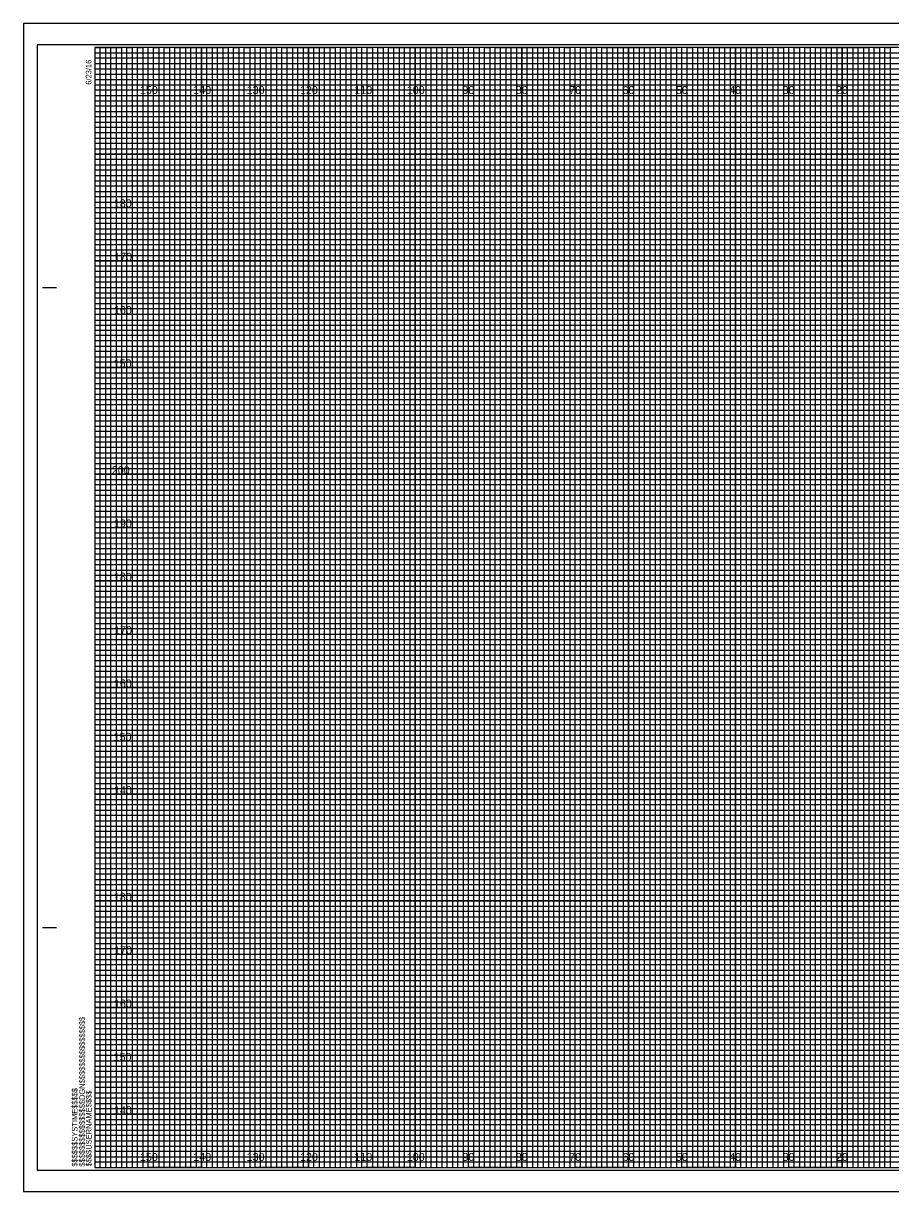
# Model space of a CAD drawing. Extents: x -13 to 323, y -5 to 434.
# Drawn here: x -13.4 to 149.1, y -4.5 to 214.5 of the extents above; entities that cross this region are included whole.
import ezdxf

# ---------------------------------------------------------------- set-up
doc = ezdxf.new("R2010")
doc.units = 0
for name, color, linetype in [('Exist Cross Section Cell', 7, 'Continuous'), ('Exist XS Center Line Elevation Label', 7, 'Continuous'), ('Exist XS Ground Line', 7, 'Continuous'), ('Prop CMT Guardrail Graphics', 7, 'Continuous'), ('Prop CMT Pvmt Course 1', 7, 'Continuous'), ('Prop CMT Pvmt Course 2', 7, 'Continuous'), ('Prop CMT Pvmt Course 3', 7, 'Continuous'), ('Prop CMT Shld Paved Course 1', 7, 'Continuous'), ('Prop CMT Shld Paved Course 2', 7, 'Continuous'), ('Prop CMT Subgrade Earthwork', 7, 'Continuous'), ('Scratch_Level_0', 7, 'Continuous')]:
    doc.layers.add(name, color=color, linetype=linetype)

msp = doc.modelspace()

# ---------------------------------------------------------------- linework, layer by layer
at = {"layer": 'Exist XS Center Line Elevation Label'}
for points in [[(0, 210), (5, 210), (5, 0), (15, 0), (15, 210), (25, 210), (25, 0), (35, 0), (35, 210), (45, 210), (45, 0), (55, 0), (55, 210), (65, 210), (65, 0), (75, 0), (75, 210), (85, 210), (85, 0), (95, 0), (95, 210), (105, 210), (105, 0), (115, 0), (115, 210), (125, 210), (125, 0), (135, 0), (135, 210), (145, 210), (145, 0), (155, 0)], [(0, 205), (275, 205)], [(0, 185), (320, 185), (320, 195), (0, 195)], [(0, 165), (320, 165), (320, 175), (0, 175)], [(0, 145), (320, 145), (320, 155), (0, 155)], [(0, 125), (320, 125), (320, 135), (0, 135)], [(0, 105), (320, 105), (320, 115), (0, 115)], [(0, 85), (320, 85), (320, 95), (0, 95)], [(0, 65), (320, 65), (320, 75), (0, 75)], [(0, 45), (320, 45), (320, 55), (0, 55)], [(0, 25), (320, 25), (320, 35), (0, 35)], [(0, 5), (320, 5), (320, 15), (0, 15)]]:
    msp.add_lwpolyline(points, dxfattribs=at)
at = {"layer": 'Exist XS Ground Line'}
for p, q in [((10, 210), (0, 210)), ((10, 0), (10, 210)), ((30, 210), (20, 210)), ((20, 210), (20, 0)), ((30, 0), (30, 210)), ((50, 210), (40, 210)), ((40, 210), (40, 0)), ((50, 0), (50, 210)), ((70, 210), (60, 210)), ((60, 210), (60, 0)), ((70, 0), (70, 210)), ((90, 210), (80, 210)), ((80, 210), (80, 0)), ((90, 0), (90, 210)), ((110, 210), (100, 210)), ((100, 210), (100, 0)), ((110, 0), (110, 210)), ((130, 210), (120, 210)), ((120, 210), (120, 0)), ((130, 0), (130, 210)), ((150, 210), (140, 210)), ((140, 210), (140, 0)), ((20, 0), (10, 0)), ((40, 0), (30, 0)), ((60, 0), (50, 0)), ((80, 0), (70, 0)), ((100, 0), (90, 0)), ((120, 0), (110, 0)), ((140, 0), (130, 0))]:
    msp.add_line(p, q, dxfattribs=at)
for points in [[(0, 200), (320, 200), (320, 190), (0, 190)], [(0, 180), (320, 180), (320, 170), (0, 170)], [(0, 160), (320, 160), (320, 150), (0, 150)], [(0, 140), (320, 140), (320, 130), (0, 130)], [(0, 120), (320, 120), (320, 110), (0, 110)], [(0, 100), (320, 100), (320, 90), (0, 90)], [(0, 80), (320, 80), (320, 70), (0, 70)], [(0, 60), (320, 60), (320, 50), (0, 50)], [(0, 40), (320, 40), (320, 30), (0, 30)], [(0, 20), (320, 20), (320, 10), (0, 10)]]:
    msp.add_lwpolyline(points, dxfattribs=at)
at = {"layer": 'Prop CMT Pvmt Course 1'}
for p, q in [((323.3, 214.5), (-13.4, 214.5)), ((-13.4, 214.5), (-13.4, -4.5)), ((-13.4, -4.5), (323.3, -4.5))]:
    msp.add_line(p, q, dxfattribs=at)
at = {"layer": 'Prop CMT Pvmt Course 2'}
msp.add_lwpolyline([(-13.4, -4.5), (323.3, -4.5), (323.3, 214.5), (-13.4, 214.5)], close=True, dxfattribs=at)
at = {"layer": 'Prop CMT Pvmt Course 3'}
msp.add_lwpolyline([(-10.8, -0.5), (322.4, -0.5), (322.4, 210.5), (-10.8, 210.5)], close=True, dxfattribs=at)
at = {"layer": 'Prop CMT Shld Paved Course 1'}
for p, q in [((-9.8, 165), (-7.3, 165)), ((-9.7, 165), (-7.2, 165)), ((-9.8, 45), (-7.3, 45)), ((-9.7, 45), (-7.2, 45)), ((0, 0), (0, 0)), ((0, 0), (0, 0)), ((0, 0), (0, 0)), ((0, 0), (0, 0)), ((0, 0), (0, 0)), ((0, 0), (0, 0)), ((0, 0), (0, 0))]:
    msp.add_line(p, q, dxfattribs=at)
msp.add_lwpolyline([(320, 210), (0, 210), (0, 0), (320, 0)], close=True, dxfattribs=at)
at = {"layer": 'Prop CMT Shld Paved Course 2'}
for points in [[(0, 0), (1, 0), (1, 210), (2, 210), (2, 0)], [(2, 0), (3, 0), (3, 210), (4, 210), (4, 0)], [(5, 0), (6, 0), (6, 210), (7, 210), (7, 0)], [(7, 0), (8, 0), (8, 210), (9, 210), (9, 0)], [(10, 0), (11, 0), (11, 210), (12, 210), (12, 0)], [(12, 0), (13, 0), (13, 210), (14, 210), (14, 0)], [(15, 0), (16, 0), (16, 210), (17, 210), (17, 0)], [(17, 0), (18, 0), (18, 210), (19, 210), (19, 0)], [(20, 0), (21, 0), (21, 210), (22, 210), (22, 0)], [(22, 0), (23, 0), (23, 210), (24, 210), (24, 0)], [(25, 0), (26, 0), (26, 210), (27, 210), (27, 0)], [(27, 0), (28, 0), (28, 210), (29, 210), (29, 0)], [(30, 0), (31, 0), (31, 210), (32, 210), (32, 0)], [(32, 0), (33, 0), (33, 210), (34, 210), (34, 0)], [(35, 0), (36, 0), (36, 210), (37, 210), (37, 0)], [(37, 0), (38, 0), (38, 210), (39, 210), (39, 0)], [(40, 0), (41, 0), (41, 210), (42, 210), (42, 0)], [(42, 0), (43, 0), (43, 210), (44, 210), (44, 0)], [(45, 0), (46, 0), (46, 210), (47, 210), (47, 0)], [(47, 0), (48, 0), (48, 210), (49, 210), (49, 0)], [(50, 0), (51, 0), (51, 210), (52, 210), (52, 0)], [(52, 0), (53, 0), (53, 210), (54, 210), (54, 0)], [(55, 0), (56, 0), (56, 210), (57, 210), (57, 0)], [(57, 0), (58, 0), (58, 210), (59, 210), (59, 0)], [(60, 0), (61, 0), (61, 210), (62, 210), (62, 0)], [(62, 0), (63, 0), (63, 210), (64, 210), (64, 0)], [(65, 0), (66, 0), (66, 210), (67, 210), (67, 0)], [(67, 0), (68, 0), (68, 210), (69, 210), (69, 0)], [(70, 0), (71, 0), (71, 210), (72, 210), (72, 0)], [(72, 0), (73, 0), (73, 210), (74, 210), (74, 0)], [(75, 0), (76, 0), (76, 210), (77, 210), (77, 0)], [(77, 0), (78, 0), (78, 210), (79, 210), (79, 0)], [(80, 0), (81, 0), (81, 210), (82, 210), (82, 0)], [(82, 0), (83, 0), (83, 210), (84, 210), (84, 0)], [(85, 0), (86, 0), (86, 210), (87, 210), (87, 0)], [(87, 0), (88, 0), (88, 210), (89, 210), (89, 0)], [(90, 0), (91, 0), (91, 210), (92, 210), (92, 0)], [(92, 0), (93, 0), (93, 210), (94, 210), (94, 0)], [(95, 0), (96, 0), (96, 210), (97, 210), (97, 0)], [(97, 0), (98, 0), (98, 210), (99, 210), (99, 0)], [(100, 0), (101, 0), (101, 210), (102, 210), (102, 0)], [(102, 0), (103, 0), (103, 210), (104, 210), (104, 0)], [(105, 0), (106, 0), (106, 210), (107, 210), (107, 0)], [(107, 0), (108, 0), (108, 210), (109, 210), (109, 0)], [(110, 0), (111, 0), (111, 210), (112, 210), (112, 0)], [(112, 0), (113, 0), (113, 210), (114, 210), (114, 0)], [(115, 0), (116, 0), (116, 210), (117, 210), (117, 0)], [(117, 0), (118, 0), (118, 210), (119, 210), (119, 0)], [(120, 0), (121, 0), (121, 210), (122, 210), (122, 0)], [(122, 0), (123, 0), (123, 210), (124, 210), (124, 0)], [(125, 0), (126, 0), (126, 210), (127, 210), (127, 0)], [(127, 0), (128, 0), (128, 210), (129, 210), (129, 0)], [(130, 0), (131, 0), (131, 210), (132, 210), (132, 0)], [(132, 0), (133, 0), (133, 210), (134, 210), (134, 0)], [(135, 0), (136, 0), (136, 210), (137, 210), (137, 0)], [(137, 0), (138, 0), (138, 210), (139, 210), (139, 0)], [(140, 0), (141, 0), (141, 210), (142, 210), (142, 0)], [(142, 0), (143, 0), (143, 210), (144, 210), (144, 0)], [(145, 0), (146, 0), (146, 210), (147, 210), (147, 0)], [(147, 0), (148, 0), (148, 210), (149, 210), (149, 0)]]:
    msp.add_lwpolyline(points, dxfattribs=at)
at = {"layer": 'Prop CMT Subgrade Earthwork'}
for p, q in [((10, 0), (10, 210)), ((20, 0), (20, 210)), ((30, 0), (30, 210)), ((40, 0), (40, 210)), ((50, 0), (50, 210)), ((60, 0), (60, 210)), ((70, 0), (70, 210)), ((80, 0), (80, 210)), ((90, 0), (90, 210)), ((100, 0), (100, 210)), ((110, 0), (110, 210)), ((120, 0), (120, 210)), ((130, 0), (130, 210)), ((140, 0), (140, 210)), ((0, 200), (320, 200)), ((0, 190), (320, 190)), ((0, 180), (320, 180)), ((0, 170), (320, 170)), ((0, 160), (320, 160)), ((0, 150), (320, 150)), ((0, 140), (320, 140)), ((0, 130), (320, 130)), ((0, 120), (320, 120)), ((0, 110), (320, 110)), ((0, 100), (320, 100)), ((0, 90), (320, 90)), ((0, 80), (320, 80)), ((0, 70), (320, 70)), ((0, 60), (320, 60)), ((0, 50), (320, 50)), ((0, 40), (320, 40)), ((0, 30), (320, 30)), ((0, 20), (320, 20)), ((0, 10), (320, 10))]:
    msp.add_line(p, q, dxfattribs=at)
at = {"layer": 'Scratch_Level_0'}
for p, q in [((0, 209), (260, 209)), ((260, 207.98), (0, 207.98)), ((0, 207.98), (0, 207)), ((0, 207), (260, 207)), ((260, 205.89), (0, 205.89)), ((0, 205.89), (0, 204)), ((0, 204), (320, 204))]:
    msp.add_line(p, q, dxfattribs=at)
for points in [[(0, 203), (270, 203), (320, 203), (320, 202), (0, 202)], [(0, 201), (320, 201), (320, 199), (0, 199)], [(0, 198), (320, 198), (320, 197), (0, 196.98)], [(0, 196), (320, 196), (320, 194), (0, 194)], [(0, 193), (320, 193), (320, 192), (0, 192)], [(0, 191), (320, 191), (320, 189), (0, 189)], [(0, 188), (320, 188), (320, 187), (0, 187)], [(0, 186), (320, 186), (320, 184), (0, 184)], [(0, 183), (320, 183), (320, 182), (0, 182)], [(0, 181), (320, 181), (320, 179), (0, 179)], [(0, 178), (320, 178), (320, 177), (0, 177)], [(0, 176), (320, 176), (320, 173.95), (320, 173), (320, 172), (0, 172)], [(0, 174), (320, 174), (320, 173), (0, 173)], [(0, 171), (320, 171), (320, 169), (0, 169.03)], [(0, 169.03), (320, 169), (320, 168), (0, 168)], [(0, 167), (320, 167), (320, 166), (0, 166)], [(0, 164), (320, 164), (320, 163), (0, 163)], [(0, 162), (320, 162), (320, 161), (0, 161)], [(-0.07, 158.89), (320, 158.89), (320, 157.88), (-0.07, 157.88)], [(0, 157), (320, 157), (320, 156), (0, 156)], [(0, 154), (320, 154), (320, 153), (0, 153)], [(0, 152), (320, 152), (320, 151), (0, 151)], [(0, 149), (320, 149), (320, 148), (0, 148)], [(0, 147), (320, 147), (320, 146), (0, 146)], [(0, 144), (320, 144), (320, 143), (0, 143)], [(0, 142), (320, 142), (320, 141), (0, 141)], [(0, 139), (320, 139), (319.99, 137.98), (0, 138)], [(0, 137), (320, 137), (320, 136), (0, 136)], [(0, 134), (320, 134), (320, 133), (0, 133)], [(0, 132), (320, 132), (320, 131), (0, 131)], [(0, 129), (320, 129), (320, 128), (0, 128)], [(0, 127), (320, 127), (320, 126), (0, 126)], [(0, 124), (320, 124), (320, 123), (0, 123)], [(0, 122), (320, 122), (320, 121), (0, 121)], [(0, 119), (320, 119), (320, 118), (0, 118)], [(0, 116.99), (320.07, 116.91), (320, 116), (0, 116)], [(0, 114), (320, 114), (320, 113), (0, 113)], [(0, 112), (320, 112), (320, 111), (0, 111)], [(0, 109), (320, 109), (320, 108), (0, 108)], [(0, 107), (320, 107), (320, 106), (0, 106)], [(0, 104), (320, 104), (320, 103), (0, 103)], [(0, 102), (320, 102), (320, 101), (0, 101)], [(0, 99), (320, 99), (320, 98), (0, 98)], [(0, 97), (320, 97), (320, 96), (0, 96)], [(0, 94), (320, 94), (320, 93), (0, 93)], [(0, 92), (320, 92), (320, 91), (0, 91)], [(0, 89), (320, 89), (320, 88), (0, 88)], [(0, 87), (320, 87), (320, 86), (0, 86)], [(0, 84), (320, 84), (320, 83), (0, 83)], [(0, 82), (320, 82), (320, 81), (0, 81)], [(0, 79), (320, 79), (319.99, 77.98), (0, 78)], [(0, 77), (320, 77), (320, 76), (0, 76)], [(0, 74), (320, 74), (320, 73), (0, 73)], [(0, 72), (320, 72), (320, 71), (0, 71)], [(0, 69), (320, 69), (320, 68), (0, 68)], [(0, 67), (320, 67), (320, 66), (0, 66)], [(0, 64), (320, 64), (320, 63), (0, 63)], [(0, 62), (320, 62), (320, 61), (0, 61)], [(0, 59), (320, 59), (320, 58), (0, 58)], [(0, 56.99), (320.07, 56.91), (320, 56), (0, 56)], [(0, 54), (320, 54), (320, 53), (0, 53)], [(0, 52), (320, 52), (320, 51), (0, 51)], [(0, 49), (320, 49), (320, 48), (0, 48)], [(0, 47), (320, 47), (320, 46), (0, 46)], [(0, 44), (320, 44), (320, 43), (0, 43)], [(0, 42), (320, 42), (320, 41), (0, 41)], [(0, 39), (320, 39), (320, 38), (0, 38)], [(0, 37), (320, 37), (320, 36), (0, 36)], [(0, 34), (320, 34), (320, 33), (0, 33)], [(0, 32), (320, 32), (320, 31), (0, 31)], [(0, 29), (320, 29), (320, 28), (0, 28)], [(0, 27), (320, 27), (320, 26), (0, 26)], [(0, 24), (320, 24), (320, 23), (0, 23)], [(0, 22), (320, 22), (320, 21), (0, 21)], [(0, 19), (320, 19), (320, 18), (0, 18)], [(0, 17), (320, 17), (320, 16), (0, 16)], [(0, 14), (320, 14), (320, 13), (0, 13)], [(0, 12), (320, 12), (320, 11), (0, 11)], [(0, 9), (320, 9), (320, 8), (0, 8)], [(0, 7), (320, 7), (320, 6), (0, 6)], [(0, 4), (320, 4), (320, 3), (0, 3)], [(0, 2), (320, 2), (320, 1), (0, 1)]]:
    msp.add_lwpolyline(points, dxfattribs=at)

# ---------------------------------------------------------------- texts
at = {"layer": 'Exist Cross Section Cell'}
for s, p in [('150', (8.44, 201.25)), ('140', (18.44, 201.25)), ('130', (28.44, 201.25)), ('120', (38.44, 201.25)), ('110', (48.62, 201.25)), ('100', (58.44, 201.25)), ('90', (68.86, 201.25)), ('80', (78.86, 201.25)), ('70', (88.86, 201.25)), ('60', (98.86, 201.25)), ('50', (108.86, 201.25)), ('40', (118.86, 201.25)), ('30', (128.86, 201.25)), ('20', (138.86, 201.25)), ('150', (8.44, 1.25)), ('140', (18.44, 1.25)), ('130', (28.44, 1.25)), ('120', (38.44, 1.25)), ('110', (48.62, 1.25)), ('100', (58.44, 1.25)), ('90', (68.86, 1.25)), ('80', (78.86, 1.25)), ('70', (88.86, 1.25)), ('60', (98.86, 1.25)), ('50', (108.86, 1.25)), ('40', (118.86, 1.25)), ('30', (128.86, 1.25)), ('20', (138.86, 1.25))]:
    msp.add_text(s, height=1.5, dxfattribs=at).set_placement(p)
at = {"layer": 'Prop CMT Guardrail Graphics'}
for s, p in [('180', (3.55, 180)), ('170', (3.61, 170)), ('160', (3.57, 160)), ('150', (3.52, 150)), ('200', (3.17, 130)), ('190', (3.57, 120)), ('180', (3.55, 110)), ('170', (3.61, 100)), ('160', (3.57, 90)), ('150', (3.52, 80)), ('140', (3.57, 70)), ('180', (3.55, 50)), ('170', (3.61, 40)), ('160', (3.57, 30)), ('150', (3.52, 20)), ('140', (3.57, 10))]:
    msp.add_text(s, height=1.5, dxfattribs=at).set_placement(p)
at = {"layer": 'Prop CMT Shld Paved Course 1'}
for s, p in [('6/23/16', (-0.65, 203)), ('$$$$$$$$$$$$$$$$DGN$$$$$$$$$$$$$$$$', (-1.88, 0.18)), ('$$$$$$SYSTIME$$$$$', (-3.26, 0.18)), ('$$$$USERNAME$$$$', (-0.62, 0.23))]:
    msp.add_text(s, height=1.05, rotation=90, dxfattribs=at).set_placement(p)

doc.saveas('drawing.dxf')
